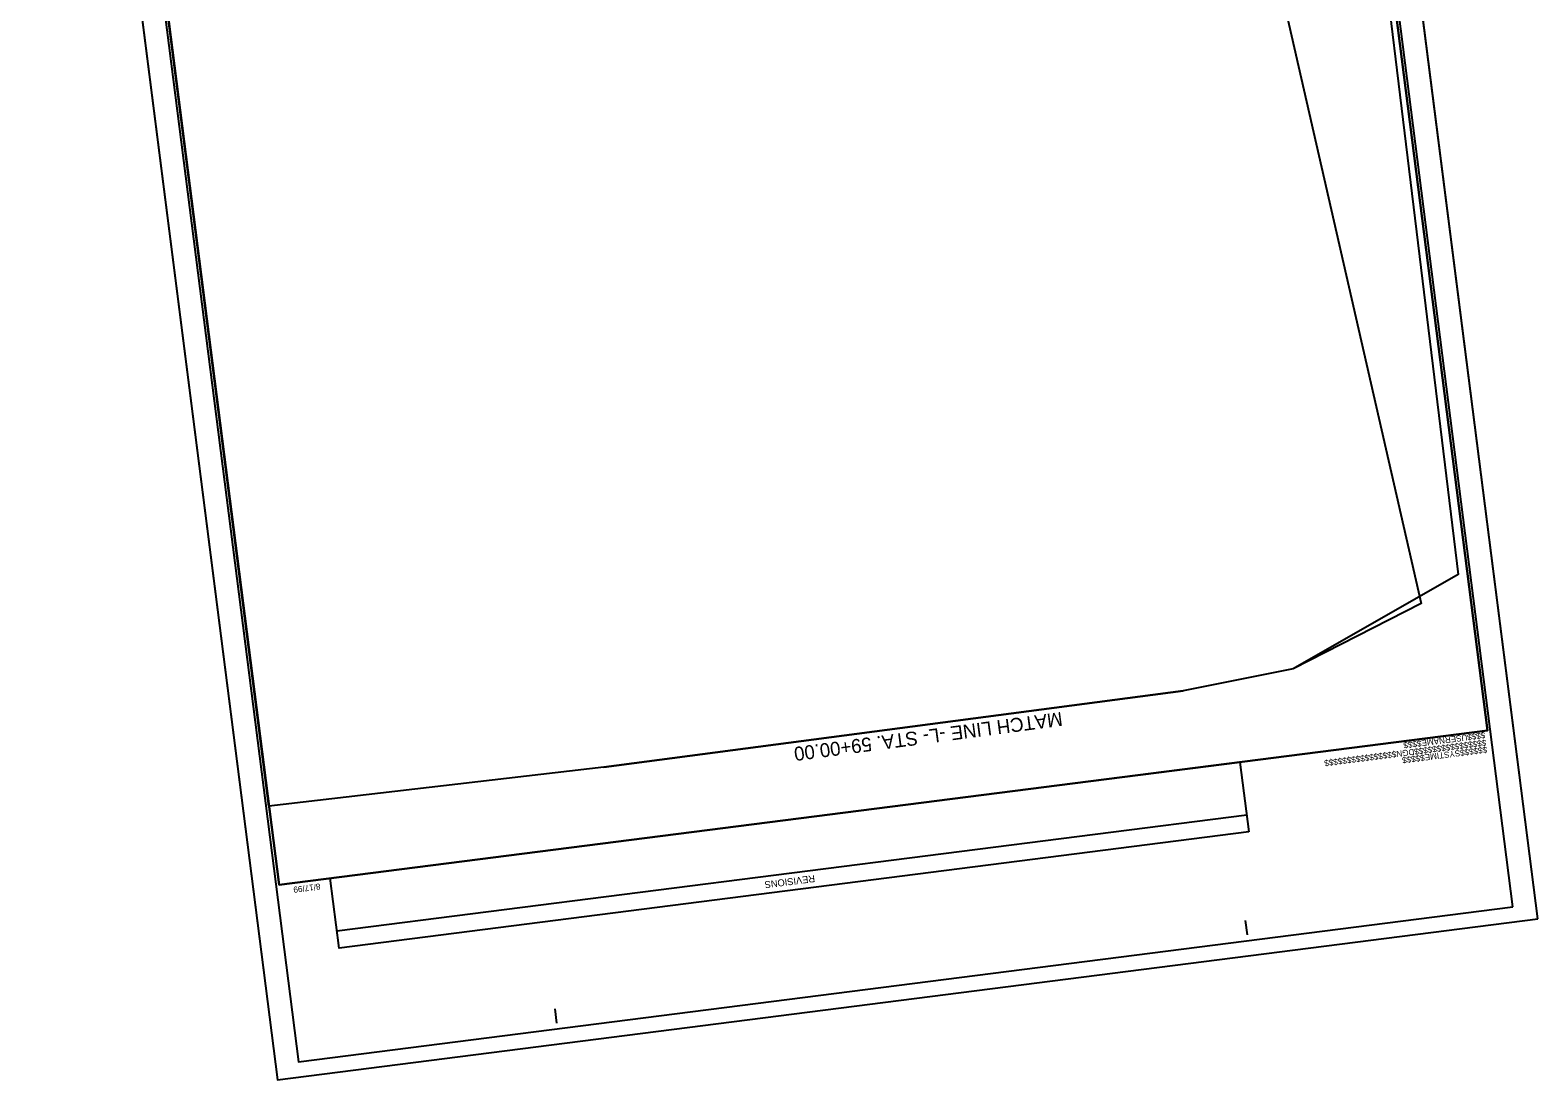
# Model space of a CAD drawing. Extents: x 2367861 to 2369161, y 805913 to 807722.
# Drawn here: x 2367861 to 2369161, y 805913 to 806817 of the extents above; entities that cross this region are included whole.
import ezdxf

# ---------------------------------------------------------------- set-up
doc = ezdxf.new("R2010")
doc.units = 0
for name, color, linetype in [('Old_Level_10', 7, 'Continuous'), ('Old_Level_15', 7, 'Continuous'), ('Old_Level_22', 7, 'Continuous'), ('Old_Level_4', 7, 'Continuous'), ('Old_Level_6', 7, 'Continuous'), ('Old_Level_61', 7, 'Continuous'), ('Old_Level_62', 7, 'Continuous'), ('Plot Shape CELL', 7, 'Continuous'), ('User Information Notes CELL', 7, 'Continuous')]:
    doc.layers.add(name, color=color, linetype=linetype)

msp = doc.modelspace()

# ---------------------------------------------------------------- linework, layer by layer
at = {"layer": 'Old_Level_10'}
msp.add_lwpolyline([(2368075.8, 806080.8), (2369117.3, 806213.9), (2368927.3, 807701.8), (2368095.5, 807595.5), (2368125.8, 807358.2), (2367916, 807331.4)], close=True, dxfattribs=at)
at = {"layer": 'Old_Level_15'}
for p, q in [((2369160.7, 806051.6), (2368947.5, 807721.5)), ((2367861.3, 807582.8), (2368074.6, 805912.8)), ((2368074.6, 805912.8), (2369160.7, 806051.6))]:
    msp.add_line(p, q, dxfattribs=at)
at = {"layer": 'Old_Level_22'}
for points in [[(2367911.1, 807370.3), (2368083.2, 807392.3), (2368175.7, 807520.9), (2368735.9, 807593.2), (2368927.3, 807701.8), (2369092.2, 806348.2), (2368949.9, 806267), (2368855, 806248.1), (2368355.6, 806182.1), (2368067.1, 806148.7)], [(2367911.1, 807370.3), (2368083.2, 807392.3), (2368175.7, 807520.9), (2368735.9, 807593.2), (2368767.4, 807604.6), (2369060.3, 806323.2), (2368949.9, 806267), (2368855, 806248.1), (2368355.6, 806182.1), (2368067.1, 806148.7)]]:
    msp.add_lwpolyline(points, close=True, dxfattribs=at)
at = {"layer": 'Old_Level_4'}
msp.add_lwpolyline([(2369139.2, 806061.9), (2368928.2, 807714.5), (2367881.7, 807580.8), (2368092.7, 805928.3)], close=True, dxfattribs=at)
at = {"layer": 'Old_Level_6'}
msp.add_lwpolyline([(2369160.7, 806051.6), (2368947.5, 807721.5), (2367861.3, 807582.8), (2368074.6, 805912.8)], close=True, dxfattribs=at)
at = {"layer": 'Old_Level_62'}
msp.add_line((2368355.6, 806182.1), (2368855, 806248.1), dxfattribs=at)
at = {"layer": 'Plot Shape CELL'}
for p, q in [((2369117.3, 806213.9), (2369117.3, 806213.9)), ((2368075.8, 806080.8), (2368075.8, 806080.8)), ((2368910.5, 806037.8), (2368908.9, 806050.2)), ((2368315.3, 805961.7), (2368313.7, 805974.1))]:
    msp.add_line(p, q, dxfattribs=at)
for points in [[(2367885.7, 807568.8), (2368075.8, 806080.8), (2369117.3, 806213.9), (2368927.3, 807701.8)], [(2369117.3, 806213.9), (2368075.8, 806080.8), (2367911.1, 807370.3), (2368059.9, 807389.3), (2368034.6, 807587.8), (2368927.3, 807701.8)]]:
    msp.add_lwpolyline(points, close=True, dxfattribs=at)
at = {"layer": 'User Information Notes CELL'}
msp.add_line((2368909.9, 806141), (2368125.6, 806040.8), dxfattribs=at)
msp.add_lwpolyline([(2368911.7, 806126.6), (2368127.5, 806026.4), (2368119.8, 806086.5), (2368904, 806186.6)], close=True, dxfattribs=at)

# ---------------------------------------------------------------- texts
at = {"layer": 'Old_Level_61'}
msp.add_text('MATCH LINE -L- STA. 59+00.00', height=12, rotation=187.5263, dxfattribs=at).set_placement((2368750.2, 806229.9))
at = {"layer": 'Plot Shape CELL'}
for s, p in [('$$$$USERNAME$$$$', (2369115.1, 806212.5)), ('$$$$$$$$$$$$$$$$DGN$$$$$$$$$$$$$$$$', (2369115.9, 806206)), ('$$$$$$SYSTIME$$$$$', (2369116.7, 806200)), ('8/17/99', (2368111.1, 806082.1))]:
    msp.add_text(s, height=5.25, rotation=187.2784, dxfattribs=at).set_placement(p)
at = {"layer": 'User Information Notes CELL'}
msp.add_text('REVISIONS', height=6, rotation=187.2784, dxfattribs=at).set_placement((2368537.3, 806089.3))

doc.saveas('drawing.dxf')
